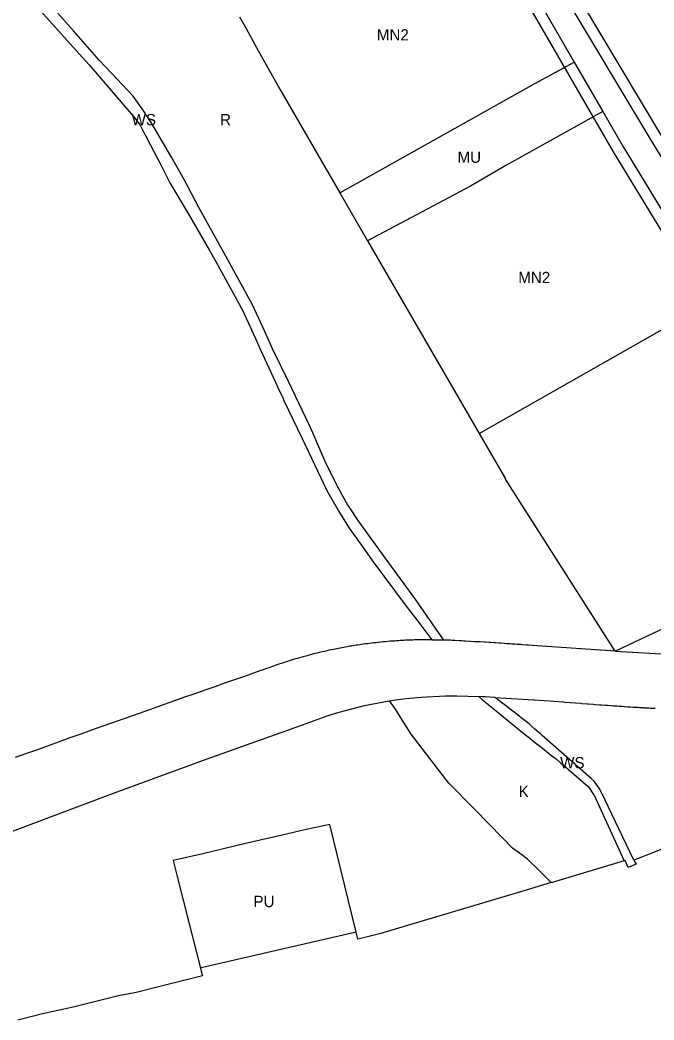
# Model space of a CAD drawing. Extents: x 7435758 to 7439981, y 5550649 to 5554049.
# Drawn here: x 7437552.2 to 7437843.8, y 5550884.6 to 5551344.8 of the extents above; entities that cross this region are included whole.
import ezdxf

# ---------------------------------------------------------------- set-up
doc = ezdxf.new("R2010")
doc.units = 0
for name, color, linetype in [('linie_rozgraniczające', 7, 'Continuous'), ('linie_zabudowy_nieprzekraczalne', 7, 'Continuous'), ('oznaczenia_przeznaczen', 7, 'Continuous')]:
    doc.layers.add(name, color=color, linetype=linetype)

msp = doc.modelspace()

# ---------------------------------------------------------------- linework, layer by layer
at = {"layer": 'linie_rozgraniczające'}
for p, q in [((7437841.65, 5551291.1), (7437789.1, 5551378.96)), ((7437576.75, 5551339.77), (7437558.29, 5551360.79)), ((7437553.16, 5551358.57), (7437579.45, 5551329.21)), ((7437789.38, 5551356.19), (7437807.13, 5551325.42)), ((7437653.21, 5551346.21), (7437656.2, 5551340.85)), ((7437656.2, 5551340.85), (7437661.21, 5551331.87)), ((7437588.58, 5551326.3), (7437576.75, 5551339.77)), ((7437661.21, 5551331.87), (7437671.69, 5551312.96)), ((7437579.45, 5551329.21), (7437583.99, 5551324.14)), ((7437583.99, 5551324.14), (7437585.86, 5551321.97)), ((7437594.24, 5551320.31), (7437588.58, 5551326.3)), ((7437789.07, 5551315.52), (7437807.13, 5551325.42)), ((7437807.13, 5551325.42), (7437820.24, 5551302.69)), ((7437585.86, 5551321.97), (7437601.54, 5551303.77)), ((7437604.27, 5551309.7), (7437594.24, 5551320.31)), ((7437671.69, 5551312.96), (7437699.26, 5551265.31)), ((7437699.26, 5551265.31), (7437789.07, 5551315.52)), ((7437609.17, 5551302.88), (7437604.27, 5551309.7)), ((7437601.54, 5551303.77), (7437604.53, 5551300.31)), ((7437604.53, 5551300.31), (7437607.51, 5551296.36)), ((7437610.86, 5551300.24), (7437609.17, 5551302.88)), ((7437612.06, 5551298.38), (7437610.86, 5551300.24)), ((7437820.24, 5551302.69), (7437775.73, 5551277.89)), ((7437820.24, 5551302.69), (7437829.46, 5551286.7)), ((7437607.51, 5551296.36), (7437609.23, 5551293.08)), ((7437621.89, 5551281.71), (7437612.06, 5551298.38)), ((7437609.23, 5551293.08), (7437610.55, 5551290.55)), ((7437610.55, 5551290.55), (7437610.6, 5551290.45)), ((7437610.6, 5551290.45), (7437616.72, 5551278.78)), ((7437888.41, 5551213.45), (7437841.65, 5551291.1)), ((7437829.46, 5551286.7), (7437864.51, 5551229.05)), ((7437627.8, 5551271.06), (7437621.89, 5551281.71)), ((7437616.72, 5551278.78), (7437621.18, 5551269.89)), ((7437775.73, 5551277.89), (7437759.38, 5551268.39)), ((7437621.18, 5551269.89), (7437629.59, 5551255.8)), ((7437634.54, 5551258.52), (7437627.8, 5551271.06)), ((7437759.38, 5551268.39), (7437712.09, 5551243.15)), ((7437699.26, 5551265.31), (7437712.09, 5551243.15)), ((7437646.85, 5551236.19), (7437634.54, 5551258.52)), ((7437629.59, 5551255.8), (7437639.26, 5551239)), ((7437712.09, 5551243.15), (7437763.36, 5551154.58)), ((7437639.26, 5551239), (7437642.32, 5551233.68)), ((7437659.21, 5551213.76), (7437646.85, 5551236.19)), ((7437642.32, 5551233.68), (7437654.7, 5551211.03)), ((7437763.36, 5551154.58), (7437872.41, 5551216.5)), ((7437663.84, 5551203.45), (7437659.21, 5551213.76)), ((7437654.7, 5551211.03), (7437655.52, 5551209.24)), ((7437655.52, 5551209.24), (7437660.55, 5551198.16)), ((7437667.37, 5551195.62), (7437663.84, 5551203.45)), ((7437660.55, 5551198.16), (7437662.89, 5551193.01)), ((7437668.4, 5551193.49), (7437667.37, 5551195.62)), ((7437675.67, 5551178.51), (7437668.4, 5551193.49)), ((7437662.89, 5551193.01), (7437669.55, 5551178.39)), ((7437669.55, 5551178.39), (7437670.78, 5551175.69)), ((7437670.78, 5551175.69), (7437673.05, 5551170.95)), ((7437685.29, 5551158.53), (7437675.67, 5551178.51)), ((7437673.05, 5551170.95), (7437673.64, 5551169.71)), ((7437673.64, 5551169.71), (7437682.03, 5551152.21)), ((7437686.94, 5551154.85), (7437685.29, 5551158.53)), ((7437682.03, 5551152.21), (7437693.39, 5551128.22)), ((7437693.08, 5551140.58), (7437686.94, 5551154.85)), ((7437763.36, 5551154.58), (7437775.5, 5551133.59)), ((7437693.18, 5551140.38), (7437693.08, 5551140.58)), ((7437697.99, 5551130.67), (7437693.18, 5551140.38)), ((7437775.48, 5551133.47), (7437775.5, 5551133.59)), ((7437826, 5551054.36), (7437775.48, 5551133.47)), ((7437698.13, 5551130.43), (7437697.99, 5551130.67)), ((7437703.01, 5551121.53), (7437698.13, 5551130.43)), ((7437693.39, 5551128.22), (7437698.59, 5551119.16)), ((7437703.62, 5551120.79), (7437703.01, 5551121.53)), ((7437707.68, 5551114.43), (7437703.62, 5551120.79)), ((7437698.59, 5551119.16), (7437699.13, 5551118.22)), ((7437699.13, 5551118.22), (7437703.64, 5551110.99)), ((7437703.64, 5551110.99), (7437709.56, 5551102.63)), ((7437718.93, 5551099.03), (7437707.68, 5551114.43)), ((7437950.17, 5551112.94), (7437826.06, 5551054.35)), ((7437709.56, 5551102.63), (7437714.22, 5551096.07)), ((7437734.21, 5551077.92), (7437718.93, 5551099.03)), ((7437714.22, 5551096.07), (7437729.82, 5551075.12)), ((7437729.82, 5551075.12), (7437735.13, 5551068.17)), ((7437747.22, 5551059.48), (7437734.21, 5551077.92)), ((7437735.13, 5551068.17), (7437741.67, 5551059.6)), ((7437697.13, 5551055.3), (7437696.35, 5551055.14)), ((7437697.9, 5551055.45), (7437697.13, 5551055.3)), ((7437698.68, 5551055.61), (7437697.9, 5551055.45)), ((7437699.44, 5551055.76), (7437698.68, 5551055.61)), ((7437700.21, 5551055.9), (7437699.44, 5551055.76)), ((7437700.96, 5551056.05), (7437700.21, 5551055.9)), ((7437701.72, 5551056.18), (7437700.96, 5551056.05)), ((7437702.47, 5551056.32), (7437701.72, 5551056.18)), ((7437703.22, 5551056.45), (7437702.47, 5551056.32)), ((7437703.96, 5551056.58), (7437703.22, 5551056.45)), ((7437704.7, 5551056.7), (7437703.96, 5551056.58)), ((7437705.44, 5551056.82), (7437704.7, 5551056.7)), ((7437706.17, 5551056.94), (7437705.44, 5551056.82)), ((7437706.9, 5551057.05), (7437706.17, 5551056.94)), ((7437707.62, 5551057.17), (7437706.9, 5551057.05)), ((7437708.47, 5551057.29), (7437707.62, 5551057.17)), ((7437709.34, 5551057.42), (7437708.47, 5551057.29)), ((7437710.21, 5551057.54), (7437709.34, 5551057.42)), ((7437711.1, 5551057.66), (7437710.21, 5551057.54)), ((7437712.01, 5551057.77), (7437711.1, 5551057.66)), ((7437712.93, 5551057.89), (7437712.01, 5551057.77)), ((7437713.86, 5551058), (7437712.93, 5551057.89)), ((7437714.82, 5551058.12), (7437713.86, 5551058)), ((7437715.92, 5551058.24), (7437714.82, 5551058.12)), ((7437717.02, 5551058.36), (7437715.92, 5551058.24)), ((7437718.12, 5551058.47), (7437717.02, 5551058.36)), ((7437719.22, 5551058.58), (7437718.12, 5551058.47)), ((7437720.32, 5551058.69), (7437719.22, 5551058.58)), ((7437721.42, 5551058.78), (7437720.32, 5551058.69)), ((7437722.52, 5551058.87), (7437721.42, 5551058.78)), ((7437723.62, 5551058.96), (7437722.52, 5551058.87)), ((7437724.47, 5551059.02), (7437723.62, 5551058.96)), ((7437725.31, 5551059.08), (7437724.47, 5551059.02)), ((7437726.16, 5551059.14), (7437725.31, 5551059.08)), ((7437727, 5551059.19), (7437726.16, 5551059.14)), ((7437727.84, 5551059.24), (7437727, 5551059.19)), ((7437728.68, 5551059.29), (7437727.84, 5551059.24)), ((7437729.52, 5551059.33), (7437728.68, 5551059.29)), ((7437730.35, 5551059.38), (7437729.52, 5551059.33)), ((7437731.18, 5551059.41), (7437730.35, 5551059.38)), ((7437732.02, 5551059.45), (7437731.18, 5551059.41)), ((7437732.84, 5551059.48), (7437732.02, 5551059.45)), ((7437733.67, 5551059.5), (7437732.84, 5551059.48)), ((7437734.49, 5551059.53), (7437733.67, 5551059.5)), ((7437735.32, 5551059.55), (7437734.49, 5551059.53)), ((7437736.14, 5551059.56), (7437735.32, 5551059.55)), ((7437736.95, 5551059.58), (7437736.14, 5551059.56)), ((7437737.54, 5551059.59), (7437736.95, 5551059.58)), ((7437737.96, 5551059.59), (7437737.54, 5551059.59)), ((7437738.13, 5551059.59), (7437737.96, 5551059.59)), ((7437738.72, 5551059.6), (7437738.13, 5551059.59)), ((7437738.97, 5551059.6), (7437738.72, 5551059.6)), ((7437739.31, 5551059.6), (7437738.97, 5551059.6)), ((7437739.9, 5551059.6), (7437739.31, 5551059.6)), ((7437739.97, 5551059.6), (7437739.9, 5551059.6)), ((7437740.49, 5551059.6), (7437739.97, 5551059.6)), ((7437740.98, 5551059.6), (7437740.49, 5551059.6)), ((7437741.08, 5551059.6), (7437740.98, 5551059.6)), ((7437741.67, 5551059.6), (7437741.08, 5551059.6)), ((7437741.67, 5551059.6), (7437741.98, 5551059.6)), ((7437741.98, 5551059.6), (7437742.51, 5551059.59)), ((7437742.51, 5551059.59), (7437742.99, 5551059.59)), ((7437742.99, 5551059.59), (7437743.34, 5551059.58)), ((7437743.34, 5551059.58), (7437744, 5551059.57)), ((7437744, 5551059.57), (7437744.17, 5551059.57)), ((7437744.17, 5551059.57), (7437745, 5551059.55)), ((7437745, 5551059.55), (7437745.48, 5551059.54)), ((7437745.48, 5551059.54), (7437745.54, 5551059.54)), ((7437745.54, 5551059.54), (7437745.97, 5551059.52)), ((7437745.97, 5551059.52), (7437746.08, 5551059.52)), ((7437746.08, 5551059.52), (7437746.47, 5551059.51)), ((7437746.47, 5551059.51), (7437746.65, 5551059.5)), ((7437746.65, 5551059.5), (7437746.98, 5551059.49)), ((7437746.98, 5551059.49), (7437747.22, 5551059.48)), ((7437747.5, 5551059.47), (7437747.22, 5551059.48)), ((7437747.93, 5551059.45), (7437747.5, 5551059.47)), ((7437748.04, 5551059.45), (7437747.93, 5551059.45)), ((7437748.6, 5551059.42), (7437748.04, 5551059.45)), ((7437748.67, 5551059.42), (7437748.6, 5551059.42)), ((7437749.19, 5551059.39), (7437748.67, 5551059.42)), ((7437749.45, 5551059.38), (7437749.19, 5551059.39)), ((7437750.09, 5551059.34), (7437749.45, 5551059.38)), ((7437750.29, 5551059.33), (7437750.09, 5551059.34)), ((7437751.01, 5551059.29), (7437750.29, 5551059.33)), ((7437751.09, 5551059.29), (7437751.01, 5551059.29)), ((7437751.82, 5551059.25), (7437751.09, 5551059.29)), ((7437752.17, 5551059.22), (7437751.82, 5551059.25)), ((7437754.34, 5551059.1), (7437752.17, 5551059.22)), ((7437754.44, 5551059.09), (7437754.34, 5551059.1)), ((7437755.26, 5551059.04), (7437754.44, 5551059.09)), ((7437755.38, 5551059.03), (7437755.26, 5551059.04)), ((7437756.22, 5551058.99), (7437755.38, 5551059.03)), ((7437756.27, 5551058.98), (7437756.22, 5551058.99)), ((7437757.09, 5551058.94), (7437756.27, 5551058.98)), ((7437759.17, 5551058.83), (7437757.09, 5551058.94)), ((7437759.28, 5551058.82), (7437759.17, 5551058.83)), ((7437761.29, 5551058.71), (7437759.28, 5551058.82)), ((7437761.51, 5551058.7), (7437761.29, 5551058.71)), ((7437763.45, 5551058.59), (7437761.51, 5551058.7)), ((7437763.79, 5551058.57), (7437763.45, 5551058.59)), ((7437765.67, 5551058.45), (7437763.79, 5551058.57)), ((7437766.12, 5551058.43), (7437765.67, 5551058.45)), ((7437767.93, 5551058.32), (7437766.12, 5551058.43)), ((7437768.51, 5551058.28), (7437767.93, 5551058.32)), ((7437770.25, 5551058.17), (7437768.51, 5551058.28)), ((7437770.98, 5551058.13), (7437770.25, 5551058.17)), ((7437772.65, 5551058.02), (7437770.98, 5551058.13)), ((7437773.52, 5551057.96), (7437772.65, 5551058.02)), ((7437775.12, 5551057.86), (7437773.52, 5551057.96)), ((7437776.15, 5551057.79), (7437775.12, 5551057.86)), ((7437777.47, 5551057.7), (7437776.15, 5551057.79)), ((7437778.45, 5551057.63), (7437777.47, 5551057.7)), ((7437779.92, 5551057.53), (7437778.45, 5551057.63)), ((7437780.85, 5551057.47), (7437779.92, 5551057.53)), ((7437782.5, 5551057.36), (7437780.85, 5551057.47)), ((7437783.37, 5551057.3), (7437782.5, 5551057.36)), ((7437785.24, 5551057.17), (7437783.37, 5551057.3)), ((7437786.06, 5551057.11), (7437785.24, 5551057.17)), ((7437787.82, 5551056.99), (7437786.06, 5551057.11)), ((7437826, 5551054.36), (7437787.82, 5551056.99)), ((7437679.07, 5551050.81), (7437677.84, 5551050.45)), ((7437680.25, 5551051.16), (7437679.07, 5551050.81)), ((7437681.41, 5551051.49), (7437680.25, 5551051.16)), ((7437682.53, 5551051.8), (7437681.41, 5551051.49)), ((7437683.63, 5551052.1), (7437682.53, 5551051.8)), ((7437684.7, 5551052.39), (7437683.63, 5551052.1)), ((7437685.23, 5551052.53), (7437684.7, 5551052.39)), ((7437685.75, 5551052.67), (7437685.23, 5551052.53)), ((7437686.27, 5551052.8), (7437685.75, 5551052.67)), ((7437686.79, 5551052.94), (7437686.27, 5551052.8)), ((7437687.87, 5551053.21), (7437686.79, 5551052.94)), ((7437688.96, 5551053.47), (7437687.87, 5551053.21)), ((7437690.04, 5551053.74), (7437688.96, 5551053.47)), ((7437691.14, 5551053.99), (7437690.04, 5551053.74)), ((7437692.24, 5551054.24), (7437691.14, 5551053.99)), ((7437693.34, 5551054.49), (7437692.24, 5551054.24)), ((7437694.45, 5551054.74), (7437693.34, 5551054.49)), ((7437695.56, 5551054.97), (7437694.45, 5551054.74)), ((7437696.35, 5551055.14), (7437695.56, 5551054.97)), ((7437826.06, 5551054.35), (7437826, 5551054.36)), ((7437826.06, 5551054.35), (7437831.37, 5551054.04)), ((7437831.37, 5551054.04), (7437847.05, 5551053.17)), ((7437665.1, 5551046.17), (7437664.01, 5551045.78)), ((7437666.13, 5551046.54), (7437665.1, 5551046.17)), ((7437667.06, 5551046.88), (7437666.13, 5551046.54)), ((7437667.92, 5551047.18), (7437667.06, 5551046.88)), ((7437668.74, 5551047.47), (7437667.92, 5551047.18)), ((7437669.52, 5551047.74), (7437668.74, 5551047.47)), ((7437670.27, 5551048.01), (7437669.52, 5551047.74)), ((7437671.32, 5551048.37), (7437670.27, 5551048.01)), ((7437672.33, 5551048.71), (7437671.32, 5551048.37)), ((7437673.3, 5551049.03), (7437672.33, 5551048.71)), ((7437674.25, 5551049.34), (7437673.3, 5551049.03)), ((7437675.18, 5551049.64), (7437674.25, 5551049.34)), ((7437676.08, 5551049.92), (7437675.18, 5551049.64)), ((7437676.97, 5551050.19), (7437676.08, 5551049.92)), ((7437677.4, 5551050.32), (7437676.97, 5551050.19)), ((7437677.84, 5551050.45), (7437677.4, 5551050.32)), ((7437655.43, 5551042.7), (7437650.9, 5551041.13)), ((7437662.5, 5551045.23), (7437655.43, 5551042.7)), ((7437664.01, 5551045.78), (7437662.5, 5551045.23)), ((7437641.77, 5551037.96), (7437637.18, 5551036.36)), ((7437646.35, 5551039.55), (7437641.77, 5551037.96)), ((7437650.9, 5551041.13), (7437646.35, 5551039.55)), ((7437627.93, 5551033.12), (7437623.27, 5551031.48)), ((7437632.57, 5551034.74), (7437627.93, 5551033.12)), ((7437637.18, 5551036.36), (7437632.57, 5551034.74)), ((7437724.9, 5551031.94), (7437728.33, 5551032.4)), ((7437728.33, 5551032.4), (7437728.36, 5551032.41)), ((7437728.36, 5551032.41), (7437736.78, 5551033.24)), ((7437736.78, 5551033.24), (7437747.87, 5551033.82)), ((7437747.87, 5551033.82), (7437753.14, 5551033.81)), ((7437753.14, 5551033.81), (7437763.19, 5551033.43)), ((7437763.19, 5551033.43), (7437765.12, 5551031.85)), ((7437764.88, 5551033.35), (7437763.19, 5551033.43)), ((7437766.23, 5551033.28), (7437764.88, 5551033.35)), ((7437770.67, 5551033.07), (7437766.23, 5551033.28)), ((7437771.6, 5551032.35), (7437770.67, 5551033.07)), ((7437770.67, 5551033.07), (7437788.61, 5551031.97)), ((7437773.07, 5551031.22), (7437771.6, 5551032.35)), ((7437613.87, 5551028.17), (7437609.13, 5551026.49)), ((7437618.58, 5551029.83), (7437613.87, 5551028.17)), ((7437623.27, 5551031.48), (7437618.58, 5551029.83)), ((7437698.94, 5551026.22), (7437710.65, 5551029.3)), ((7437710.65, 5551029.3), (7437719.57, 5551031.07)), ((7437719.57, 5551031.07), (7437722.02, 5551031.49)), ((7437722.02, 5551031.49), (7437722.1, 5551031.5)), ((7437722.1, 5551031.5), (7437724.9, 5551031.94)), ((7437724.9, 5551027.66), (7437722.1, 5551031.5)), ((7437728.22, 5551022.37), (7437724.9, 5551027.66)), ((7437765.12, 5551031.85), (7437771.21, 5551026.88)), ((7437775.54, 5551029.3), (7437773.07, 5551031.22)), ((7437778.28, 5551027.17), (7437775.54, 5551029.3)), ((7437788.61, 5551031.97), (7437788.81, 5551031.95)), ((7437788.81, 5551031.95), (7437802.14, 5551030.97)), ((7437802.14, 5551030.97), (7437802.75, 5551030.92)), ((7437802.75, 5551030.92), (7437810.11, 5551030.35)), ((7437810.11, 5551030.35), (7437810.41, 5551030.33)), ((7437810.41, 5551030.33), (7437813.1, 5551030.13)), ((7437813.1, 5551030.13), (7437813.63, 5551030.09)), ((7437813.63, 5551030.09), (7437816.06, 5551029.9)), ((7437816.06, 5551029.9), (7437816.77, 5551029.85)), ((7437816.77, 5551029.85), (7437818.73, 5551029.7)), ((7437818.73, 5551029.7), (7437819.61, 5551029.64)), ((7437819.61, 5551029.64), (7437821.55, 5551029.49)), ((7437821.55, 5551029.49), (7437822.5, 5551029.43)), ((7437822.5, 5551029.43), (7437824.2, 5551029.3)), ((7437824.2, 5551029.3), (7437825.23, 5551029.23)), ((7437825.23, 5551029.23), (7437826.73, 5551029.13)), ((7437826.73, 5551029.13), (7437827.82, 5551029.05)), ((7437827.82, 5551029.05), (7437829.15, 5551028.96)), ((7437829.15, 5551028.96), (7437830.32, 5551028.89)), ((7437830.32, 5551028.89), (7437830.42, 5551028.88)), ((7437830.42, 5551028.88), (7437831.67, 5551028.8)), ((7437831.67, 5551028.8), (7437832.66, 5551028.73)), ((7437832.66, 5551028.73), (7437832.9, 5551028.72)), ((7437832.9, 5551028.72), (7437834.11, 5551028.64)), ((7437834.11, 5551028.64), (7437834.93, 5551028.59)), ((7437834.93, 5551028.59), (7437835.3, 5551028.57)), ((7437835.3, 5551028.57), (7437836.47, 5551028.5)), ((7437836.47, 5551028.5), (7437837.14, 5551028.46)), ((7437837.14, 5551028.46), (7437837.63, 5551028.43)), ((7437837.63, 5551028.43), (7437838.78, 5551028.37)), ((7437838.78, 5551028.37), (7437839.3, 5551028.34)), ((7437839.3, 5551028.34), (7437839.91, 5551028.3)), ((7437839.91, 5551028.3), (7437840.37, 5551028.28)), ((7437840.37, 5551028.28), (7437841.03, 5551028.24)), ((7437841.03, 5551028.24), (7437841.42, 5551028.22)), ((7437841.42, 5551028.22), (7437842.14, 5551028.18)), ((7437842.14, 5551028.18), (7437842.46, 5551028.17)), ((7437842.46, 5551028.17), (7437843.24, 5551028.13)), ((7437843.24, 5551028.13), (7437843.49, 5551028.11)), ((7437843.49, 5551028.11), (7437844.33, 5551028.07)), ((7437599.58, 5551023.11), (7437594.76, 5551021.39)), ((7437604.37, 5551024.81), (7437599.58, 5551023.11)), ((7437609.13, 5551026.49), (7437604.37, 5551024.81)), ((7437678.77, 5551019.29), (7437693.9, 5551024.66)), ((7437693.9, 5551024.66), (7437698.94, 5551026.22)), ((7437771.21, 5551026.88), (7437781.67, 5551018.34)), ((7437780.09, 5551025.78), (7437778.28, 5551027.17)), ((7437782.01, 5551024.29), (7437780.09, 5551025.78)), ((7437784.53, 5551022.33), (7437782.01, 5551024.29)), ((7437589.92, 5551019.67), (7437585.04, 5551017.93)), ((7437594.76, 5551021.39), (7437589.92, 5551019.67)), ((7437638.29, 5551004.74), (7437678.77, 5551019.29)), ((7437732.17, 5551016.07), (7437728.22, 5551022.37)), ((7437785.82, 5551021.33), (7437784.53, 5551022.33)), ((7437786.49, 5551020.75), (7437785.82, 5551021.33)), ((7437787.64, 5551019.73), (7437786.49, 5551020.75)), ((7437789.07, 5551018.48), (7437787.64, 5551019.73)), ((7437791.76, 5551016.12), (7437789.07, 5551018.48)), ((7437575.2, 5551014.41), (7437570.23, 5551012.62)), ((7437580.13, 5551016.17), (7437575.2, 5551014.41)), ((7437585.04, 5551017.93), (7437580.13, 5551016.17)), ((7437740.7, 5551004.95), (7437732.17, 5551016.07)), ((7437781.67, 5551018.34), (7437785.62, 5551015.12)), ((7437785.62, 5551015.12), (7437785.64, 5551015)), ((7437785.64, 5551015), (7437785.76, 5551015.01)), ((7437785.76, 5551015.01), (7437787.93, 5551013.29)), ((7437792.43, 5551015.53), (7437791.76, 5551016.12)), ((7437814.91, 5550995.78), (7437792.43, 5551015.53)), ((7437565.24, 5551010.83), (7437560.2, 5551009.01)), ((7437570.23, 5551012.62), (7437565.24, 5551010.83)), ((7437787.93, 5551013.29), (7437792.46, 5551009.71)), ((7437792.46, 5551009.71), (7437796.84, 5551006.25)), ((7437555.13, 5551007.18), (7437550.02, 5551005.34)), ((7437560.2, 5551009.01), (7437555.13, 5551007.18)), ((7437595.18, 5550988.94), (7437638.29, 5551004.73)), ((7437638.29, 5551004.73), (7437638.29, 5551004.74)), ((7437740.7, 5551004.94), (7437740.7, 5551004.95)), ((7437749.4, 5550993.63), (7437740.7, 5551004.94)), ((7437796.84, 5551006.25), (7437798.75, 5551004.74)), ((7437798.75, 5551004.74), (7437801.04, 5551002.78)), ((7437801.04, 5551002.78), (7437803.07, 5551001.05)), ((7437803.07, 5551001.05), (7437806.82, 5550997.84)), ((7437806.82, 5550997.84), (7437813.73, 5550991.94)), ((7437816.37, 5550994.5), (7437814.91, 5550995.78)), ((7437761.2, 5550981.59), (7437749.4, 5550993.63)), ((7437813.73, 5550991.94), (7437816.02, 5550988.33)), ((7437816.64, 5550994.11), (7437816.37, 5550994.5)), ((7437818.87, 5550990.85), (7437816.64, 5550994.11)), ((7437821.35, 5550985.7), (7437818.87, 5550990.85)), ((7437509.95, 5550957.05), (7437595.18, 5550988.94)), ((7437816.02, 5550988.33), (7437816.23, 5550988.13)), ((7437816.23, 5550988.13), (7437830.07, 5550957.87)), ((7437774.13, 5550968.39), (7437761.2, 5550981.59)), ((7437827.62, 5550972.61), (7437821.35, 5550985.7)), ((7437694.74, 5550974.55), (7437683.23, 5550972.14)), ((7437706.77, 5550925.06), (7437694.74, 5550974.55)), ((7437834.56, 5550958.16), (7437827.62, 5550972.61)), ((7437672.77, 5550969.67), (7437655.91, 5550965.85)), ((7437683.23, 5550972.14), (7437672.77, 5550969.67)), ((7437778.71, 5550963.71), (7437774.13, 5550968.39)), ((7437864.51, 5550969.99), (7437840.8, 5550960.67)), ((7437655.91, 5550965.85), (7437636.29, 5550961.12)), ((7437783.01, 5550960.62), (7437778.71, 5550963.71)), ((7437636.29, 5550961.12), (7437622.59, 5550957.99)), ((7437785.7, 5550958.68), (7437783.01, 5550960.62)), ((7437790.65, 5550953.69), (7437785.7, 5550958.68)), ((7437838.51, 5550959.77), (7437834.56, 5550958.16)), ((7437840.8, 5550960.67), (7437838.51, 5550959.77)), ((7437622.59, 5550957.99), (7437624.48, 5550950.57)), ((7437830.07, 5550957.87), (7437796.96, 5550947.96)), ((7437830.56, 5550958.02), (7437830.07, 5550957.87)), ((7437831.89, 5550954.85), (7437830.56, 5550958.02)), ((7437835.66, 5550956.31), (7437831.89, 5550954.85)), ((7437834.56, 5550958.16), (7437835.66, 5550956.31)), ((7437624.48, 5550950.57), (7437629.71, 5550930.02)), ((7437796.47, 5550947.82), (7437790.65, 5550953.69)), ((7437796.47, 5550947.82), (7437785.08, 5550944.4)), ((7437796.96, 5550947.96), (7437796.47, 5550947.82)), ((7437785.08, 5550944.4), (7437717.56, 5550924.19)), ((7437629.71, 5550930.02), (7437635.19, 5550908.51)), ((7437706.77, 5550925.06), (7437635.58, 5550908.6)), ((7437707.57, 5550921.74), (7437706.77, 5550925.06)), ((7437708.29, 5550921.92), (7437707.57, 5550921.74)), ((7437717.56, 5550924.19), (7437708.29, 5550921.92)), ((7437635.58, 5550908.6), (7437635.19, 5550908.51)), ((7437635.19, 5550908.51), (7437635.56, 5550907.05)), ((7437636.09, 5550904.97), (7437619.64, 5550900.82)), ((7437635.56, 5550907.05), (7437636.09, 5550904.97)), ((7437619.64, 5550900.82), (7437605.06, 5550897.15)), ((7437597.53, 5550895.76), (7437576.65, 5550890.57)), ((7437604.87, 5550897.1), (7437597.53, 5550895.76)), ((7437605.06, 5550897.15), (7437604.87, 5550897.1)), ((7437576.65, 5550890.57), (7437562.64, 5550887.41)), ((7437562.64, 5550887.41), (7437551.28, 5550884.61))]:
    msp.add_line(p, q, dxfattribs=at)
at = {"layer": 'linie_zabudowy_nieprzekraczalne'}
for points in [[(7437945.38, 5551110.68), (7437944.16, 5551111.91), (7437944.1, 5551111.98), (7437943.99, 5551112.09), (7437920.13, 5551138.79), (7437920.01, 5551138.92), (7437904.28, 5551157.81), (7437904.08, 5551158.06), (7437903.98, 5551158.2), (7437894.29, 5551172.45), (7437894.2, 5551172.59), (7437880.46, 5551194.33), (7437880.46, 5551194.33), (7437860.28, 5551226.39), (7437860.24, 5551226.45), (7437825.19, 5551284.1), (7437825.13, 5551284.2), (7437785.07, 5551353.65), (7437753.35, 5551406.01), (7437753.34, 5551406.04), (7437746.65, 5551417.27), (7437742.73, 5551423.43)], [(7437793.4, 5551381.52), (7437845.93, 5551293.68), (7437891.6, 5551217.86), (7437895.22, 5551211.84), (7437899.6, 5551204.71), (7437903.43, 5551198.8), (7437920.94, 5551171.83), (7437929.95, 5551161.08), (7437956.8, 5551130.1), (7437979.4, 5551107.07), (7437979.59, 5551106.9), (7437979.69, 5551106.81), (7437982.45, 5551104.12), (7437990.7, 5551102.18), (7437996.04, 5551103.81), (7437996.06, 5551103.82), (7438059.45, 5551124), (7438084.33, 5551131.93), (7438088.83, 5551133.36)]]:
    msp.add_lwpolyline(points, dxfattribs=at)

# ---------------------------------------------------------------- texts
at = {"layer": 'oznaczenia_przeznaczen'}
for s, p in [('MN2', (7437716.35, 5551335.37)), ('WS', (7437603.57, 5551296.35)), ('R', (7437644.25, 5551296.34)), ('MU', (7437753.46, 5551279.07)), ('MN2', (7437781.4, 5551223.71)), ('WS', (7437800.67, 5551000.42)), ('K', (7437781.55, 5550987.24)), ('PU', (7437659.61, 5550936.56))]:
    msp.add_text(s, height=5.2, dxfattribs=at).set_placement(p)

doc.saveas('drawing.dxf')
